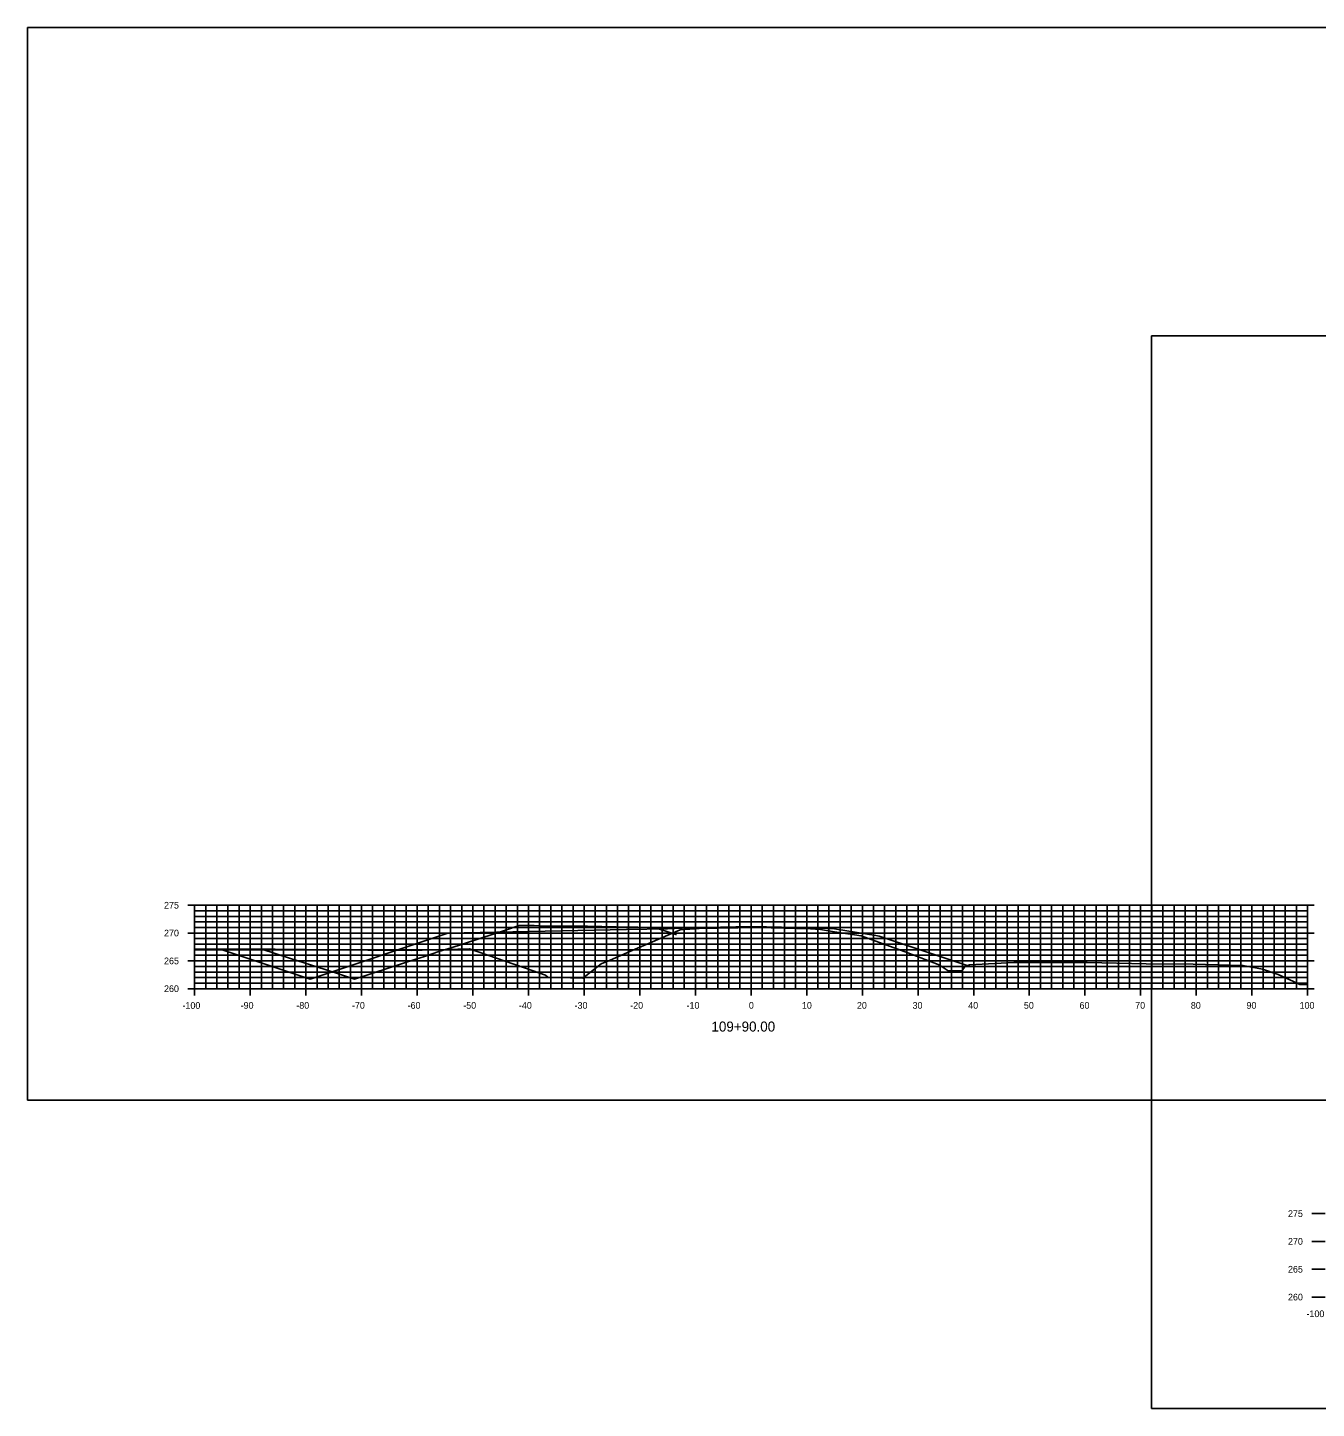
# Model space of a CAD drawing. Extents: x 1661012 to 1662122, y 670053 to 671852.
# Drawn here: x 1661032.7 to 1661264.3, y 671488.8 to 671736.9 of the extents above; entities that cross this region are included whole.
import ezdxf

# ---------------------------------------------------------------- set-up
doc = ezdxf.new("R2010")
doc.units = 0
for name, color, linetype in [('R_Concrete', 7, 'Continuous'), ('R_Concrete Hidden', 7, 'Continuous'), ('R_Erosion', 7, 'Continuous'), ('R_Exist Surface', 7, 'Continuous'), ('R_Proposed Road', 7, 'Continuous'), ('R_ROW Annot', 7, 'Continuous')]:
    doc.layers.add(name, color=color, linetype=linetype)

msp = doc.modelspace()

# ---------------------------------------------------------------- linework, layer by layer
at = {"layer": 'R_Concrete'}
for p, q in [((1661061.47, 671579.25), (1661063.87, 671579.25)), ((1661062.67, 671579.25), (1661262.67, 671579.25)), ((1661062.67, 671564.25), (1661062.67, 671579.25)), ((1661062.67, 671564.25), (1661062.67, 671579.25)), ((1661064.67, 671564.25), (1661064.67, 671579.25)), ((1661066.67, 671564.25), (1661066.67, 671579.25)), ((1661068.67, 671564.25), (1661068.67, 671579.25)), ((1661070.67, 671564.25), (1661070.67, 671579.25)), ((1661072.67, 671564.25), (1661072.67, 671579.25)), ((1661074.67, 671564.25), (1661074.67, 671579.25)), ((1661076.67, 671564.25), (1661076.67, 671579.25)), ((1661078.67, 671564.25), (1661078.67, 671579.25)), ((1661080.67, 671564.25), (1661080.67, 671579.25)), ((1661082.67, 671564.25), (1661082.67, 671579.25)), ((1661084.67, 671564.25), (1661084.67, 671579.25)), ((1661086.67, 671564.25), (1661086.67, 671579.25)), ((1661088.67, 671564.25), (1661088.67, 671579.25)), ((1661090.67, 671564.25), (1661090.67, 671579.25)), ((1661092.67, 671564.25), (1661092.67, 671579.25)), ((1661094.67, 671564.25), (1661094.67, 671579.25)), ((1661096.67, 671564.25), (1661096.67, 671579.25)), ((1661098.67, 671564.25), (1661098.67, 671579.25)), ((1661100.67, 671564.25), (1661100.67, 671579.25)), ((1661102.67, 671564.25), (1661102.67, 671579.25)), ((1661104.67, 671564.25), (1661104.67, 671579.25)), ((1661106.67, 671564.25), (1661106.67, 671579.25)), ((1661108.67, 671564.25), (1661108.67, 671579.25)), ((1661110.67, 671564.25), (1661110.67, 671579.25)), ((1661112.67, 671564.25), (1661112.67, 671579.25)), ((1661114.67, 671564.25), (1661114.67, 671579.25)), ((1661116.67, 671564.25), (1661116.67, 671579.25)), ((1661118.67, 671564.25), (1661118.67, 671579.25)), ((1661120.67, 671564.25), (1661120.67, 671579.25)), ((1661122.67, 671564.25), (1661122.67, 671579.25)), ((1661124.67, 671564.25), (1661124.67, 671579.25)), ((1661126.67, 671564.25), (1661126.67, 671579.25)), ((1661128.67, 671564.25), (1661128.67, 671579.25)), ((1661130.67, 671564.25), (1661130.67, 671579.25)), ((1661132.67, 671564.25), (1661132.67, 671579.25)), ((1661134.67, 671564.25), (1661134.67, 671579.25)), ((1661136.67, 671564.25), (1661136.67, 671579.25)), ((1661138.67, 671564.25), (1661138.67, 671579.25)), ((1661140.67, 671564.25), (1661140.67, 671579.25)), ((1661142.67, 671564.25), (1661142.67, 671579.25)), ((1661144.67, 671564.25), (1661144.67, 671579.25)), ((1661146.67, 671564.25), (1661146.67, 671579.25)), ((1661148.67, 671564.25), (1661148.67, 671579.25)), ((1661150.67, 671564.25), (1661150.67, 671579.25)), ((1661152.67, 671564.25), (1661152.67, 671579.25)), ((1661154.67, 671564.25), (1661154.67, 671579.25)), ((1661156.67, 671564.25), (1661156.67, 671579.25)), ((1661158.67, 671564.25), (1661158.67, 671579.25)), ((1661160.67, 671564.25), (1661160.67, 671579.25)), ((1661162.67, 671564.25), (1661162.67, 671579.25)), ((1661164.67, 671564.25), (1661164.67, 671579.25)), ((1661166.67, 671564.25), (1661166.67, 671579.25)), ((1661168.67, 671564.25), (1661168.67, 671579.25)), ((1661170.67, 671564.25), (1661170.67, 671579.25)), ((1661172.67, 671564.25), (1661172.67, 671579.25)), ((1661174.67, 671564.25), (1661174.67, 671579.25)), ((1661176.67, 671564.25), (1661176.67, 671579.25)), ((1661178.67, 671564.25), (1661178.67, 671579.25)), ((1661180.67, 671564.25), (1661180.67, 671579.25)), ((1661182.67, 671564.25), (1661182.67, 671579.25)), ((1661184.67, 671564.25), (1661184.67, 671579.25)), ((1661186.67, 671564.25), (1661186.67, 671579.25)), ((1661188.67, 671564.25), (1661188.67, 671579.25)), ((1661190.67, 671564.25), (1661190.67, 671579.25)), ((1661192.67, 671564.25), (1661192.67, 671579.25)), ((1661194.67, 671564.25), (1661194.67, 671579.25)), ((1661196.67, 671564.25), (1661196.67, 671579.25)), ((1661198.67, 671564.25), (1661198.67, 671579.25)), ((1661200.67, 671564.25), (1661200.67, 671579.25)), ((1661202.67, 671564.25), (1661202.67, 671579.25)), ((1661204.67, 671564.25), (1661204.67, 671579.25)), ((1661206.67, 671564.25), (1661206.67, 671579.25)), ((1661208.67, 671564.25), (1661208.67, 671579.25)), ((1661210.67, 671564.25), (1661210.67, 671579.25)), ((1661212.67, 671564.25), (1661212.67, 671579.25)), ((1661214.67, 671564.25), (1661214.67, 671579.25)), ((1661216.67, 671564.25), (1661216.67, 671579.25)), ((1661218.67, 671564.25), (1661218.67, 671579.25)), ((1661220.67, 671564.25), (1661220.67, 671579.25)), ((1661222.67, 671564.25), (1661222.67, 671579.25)), ((1661224.67, 671564.25), (1661224.67, 671579.25)), ((1661226.67, 671564.25), (1661226.67, 671579.25)), ((1661228.67, 671564.25), (1661228.67, 671579.25)), ((1661230.67, 671564.25), (1661230.67, 671579.25)), ((1661232.67, 671564.25), (1661232.67, 671579.25)), ((1661234.67, 671564.25), (1661234.67, 671579.25)), ((1661236.67, 671564.25), (1661236.67, 671579.25)), ((1661238.67, 671564.25), (1661238.67, 671579.25)), ((1661240.67, 671564.25), (1661240.67, 671579.25)), ((1661242.67, 671564.25), (1661242.67, 671579.25)), ((1661244.67, 671564.25), (1661244.67, 671579.25)), ((1661246.67, 671564.25), (1661246.67, 671579.25)), ((1661248.67, 671564.25), (1661248.67, 671579.25)), ((1661250.67, 671564.25), (1661250.67, 671579.25)), ((1661252.67, 671564.25), (1661252.67, 671579.25)), ((1661254.67, 671564.25), (1661254.67, 671579.25)), ((1661256.67, 671564.25), (1661256.67, 671579.25)), ((1661258.67, 671564.25), (1661258.67, 671579.25)), ((1661260.67, 671564.25), (1661260.67, 671579.25)), ((1661263.87, 671579.25), (1661261.47, 671579.25)), ((1661262.67, 671564.25), (1661262.67, 671579.25)), ((1661062.67, 671578.25), (1661262.67, 671578.25)), ((1661062.67, 671578.25), (1661063.27, 671578.25)), ((1661062.67, 671577.25), (1661262.67, 671577.25)), ((1661062.67, 671577.25), (1661063.27, 671577.25)), ((1661262.67, 671578.25), (1661262.07, 671578.25)), ((1661262.67, 671577.25), (1661262.07, 671577.25)), ((1661061.47, 671574.25), (1661063.87, 671574.25)), ((1661062.67, 671576.25), (1661262.67, 671576.25)), ((1661062.67, 671576.25), (1661063.27, 671576.25)), ((1661062.67, 671575.25), (1661262.67, 671575.25)), ((1661062.67, 671575.25), (1661063.27, 671575.25)), ((1661062.67, 671574.25), (1661262.67, 671574.25)), ((1661263.87, 671574.25), (1661261.47, 671574.25)), ((1661262.67, 671576.25), (1661262.07, 671576.25)), ((1661262.67, 671575.25), (1661262.07, 671575.25)), ((1661062.67, 671573.25), (1661262.67, 671573.25)), ((1661062.67, 671573.25), (1661063.27, 671573.25)), ((1661062.67, 671572.25), (1661262.67, 671572.25)), ((1661062.67, 671572.25), (1661063.27, 671572.25)), ((1661262.67, 671573.25), (1661262.07, 671573.25)), ((1661262.67, 671572.25), (1661262.07, 671572.25)), ((1661061.47, 671569.25), (1661063.87, 671569.25)), ((1661062.67, 671571.25), (1661262.67, 671571.25)), ((1661062.67, 671571.25), (1661063.27, 671571.25)), ((1661062.67, 671570.25), (1661262.67, 671570.25)), ((1661062.67, 671570.25), (1661063.27, 671570.25)), ((1661062.67, 671569.25), (1661262.67, 671569.25)), ((1661263.87, 671569.25), (1661261.47, 671569.25)), ((1661262.67, 671571.25), (1661262.07, 671571.25)), ((1661262.67, 671570.25), (1661262.07, 671570.25)), ((1661062.67, 671568.25), (1661262.67, 671568.25)), ((1661062.67, 671568.25), (1661063.27, 671568.25)), ((1661062.67, 671567.25), (1661262.67, 671567.25)), ((1661062.67, 671567.25), (1661063.27, 671567.25)), ((1661262.67, 671568.25), (1661262.07, 671568.25)), ((1661262.67, 671567.25), (1661262.07, 671567.25)), ((1661061.47, 671564.25), (1661063.87, 671564.25)), ((1661062.67, 671566.25), (1661262.67, 671566.25)), ((1661062.67, 671566.25), (1661063.27, 671566.25)), ((1661062.67, 671563.05), (1661062.67, 671565.45)), ((1661062.67, 671565.25), (1661262.67, 671565.25)), ((1661062.67, 671565.25), (1661063.27, 671565.25)), ((1661062.67, 671564.25), (1661062.67, 671564.85)), ((1661062.67, 671564.25), (1661262.67, 671564.25)), ((1661064.67, 671564.25), (1661064.67, 671564.85)), ((1661066.67, 671564.25), (1661066.67, 671564.85)), ((1661068.67, 671564.25), (1661068.67, 671564.85)), ((1661070.67, 671564.25), (1661070.67, 671564.85)), ((1661072.67, 671563.05), (1661072.67, 671565.45)), ((1661074.67, 671564.25), (1661074.67, 671564.85)), ((1661076.67, 671564.25), (1661076.67, 671564.85)), ((1661078.67, 671564.25), (1661078.67, 671564.85)), ((1661080.67, 671564.25), (1661080.67, 671564.85)), ((1661082.67, 671563.05), (1661082.67, 671565.45)), ((1661084.67, 671564.25), (1661084.67, 671564.85)), ((1661086.67, 671564.25), (1661086.67, 671564.85)), ((1661088.67, 671564.25), (1661088.67, 671564.85)), ((1661090.67, 671564.25), (1661090.67, 671564.85)), ((1661092.67, 671563.05), (1661092.67, 671565.45)), ((1661094.67, 671564.25), (1661094.67, 671564.85)), ((1661096.67, 671564.25), (1661096.67, 671564.85)), ((1661098.67, 671564.25), (1661098.67, 671564.85)), ((1661100.67, 671564.25), (1661100.67, 671564.85)), ((1661102.67, 671563.05), (1661102.67, 671565.45)), ((1661104.67, 671564.25), (1661104.67, 671564.85)), ((1661106.67, 671564.25), (1661106.67, 671564.85)), ((1661108.67, 671564.25), (1661108.67, 671564.85)), ((1661110.67, 671564.25), (1661110.67, 671564.85)), ((1661112.67, 671563.05), (1661112.67, 671565.45)), ((1661114.67, 671564.25), (1661114.67, 671564.85)), ((1661116.67, 671564.25), (1661116.67, 671564.85)), ((1661118.67, 671564.25), (1661118.67, 671564.85)), ((1661120.67, 671564.25), (1661120.67, 671564.85)), ((1661122.67, 671563.05), (1661122.67, 671565.45)), ((1661124.67, 671564.25), (1661124.67, 671564.85)), ((1661126.67, 671564.25), (1661126.67, 671564.85)), ((1661128.67, 671564.25), (1661128.67, 671564.85)), ((1661130.67, 671564.25), (1661130.67, 671564.85)), ((1661132.67, 671563.05), (1661132.67, 671565.45)), ((1661134.67, 671564.25), (1661134.67, 671564.85)), ((1661136.67, 671564.25), (1661136.67, 671564.85)), ((1661138.67, 671564.25), (1661138.67, 671564.85)), ((1661140.67, 671564.25), (1661140.67, 671564.85)), ((1661142.67, 671563.05), (1661142.67, 671565.45)), ((1661144.67, 671564.25), (1661144.67, 671564.85)), ((1661146.67, 671564.25), (1661146.67, 671564.85)), ((1661148.67, 671564.25), (1661148.67, 671564.85)), ((1661150.67, 671564.25), (1661150.67, 671564.85)), ((1661152.67, 671563.05), (1661152.67, 671565.45)), ((1661154.67, 671564.25), (1661154.67, 671564.85)), ((1661156.67, 671564.25), (1661156.67, 671564.85)), ((1661158.67, 671564.25), (1661158.67, 671564.85)), ((1661160.67, 671564.25), (1661160.67, 671564.85)), ((1661162.67, 671563.05), (1661162.67, 671565.45)), ((1661164.67, 671564.25), (1661164.67, 671564.85)), ((1661166.67, 671564.25), (1661166.67, 671564.85)), ((1661168.67, 671564.25), (1661168.67, 671564.85)), ((1661170.67, 671564.25), (1661170.67, 671564.85)), ((1661172.67, 671563.05), (1661172.67, 671565.45)), ((1661174.67, 671564.25), (1661174.67, 671564.85)), ((1661176.67, 671564.25), (1661176.67, 671564.85)), ((1661178.67, 671564.25), (1661178.67, 671564.85)), ((1661180.67, 671564.25), (1661180.67, 671564.85)), ((1661182.67, 671563.05), (1661182.67, 671565.45)), ((1661184.67, 671564.25), (1661184.67, 671564.85)), ((1661186.67, 671564.25), (1661186.67, 671564.85)), ((1661188.67, 671564.25), (1661188.67, 671564.85)), ((1661190.67, 671564.25), (1661190.67, 671564.85)), ((1661192.67, 671563.05), (1661192.67, 671565.45)), ((1661194.67, 671564.25), (1661194.67, 671564.85)), ((1661196.67, 671564.25), (1661196.67, 671564.85)), ((1661198.67, 671564.25), (1661198.67, 671564.85)), ((1661200.67, 671564.25), (1661200.67, 671564.85)), ((1661202.67, 671563.05), (1661202.67, 671565.45)), ((1661204.67, 671564.25), (1661204.67, 671564.85)), ((1661206.67, 671564.25), (1661206.67, 671564.85)), ((1661208.67, 671564.25), (1661208.67, 671564.85)), ((1661210.67, 671564.25), (1661210.67, 671564.85)), ((1661212.67, 671563.05), (1661212.67, 671565.45)), ((1661214.67, 671564.25), (1661214.67, 671564.85)), ((1661216.67, 671564.25), (1661216.67, 671564.85)), ((1661218.67, 671564.25), (1661218.67, 671564.85)), ((1661220.67, 671564.25), (1661220.67, 671564.85)), ((1661222.67, 671563.05), (1661222.67, 671565.45)), ((1661224.67, 671564.25), (1661224.67, 671564.85)), ((1661226.67, 671564.25), (1661226.67, 671564.85)), ((1661228.67, 671564.25), (1661228.67, 671564.85)), ((1661230.67, 671564.25), (1661230.67, 671564.85)), ((1661232.67, 671563.05), (1661232.67, 671565.45)), ((1661234.67, 671564.25), (1661234.67, 671564.85)), ((1661236.67, 671564.25), (1661236.67, 671564.85)), ((1661238.67, 671564.25), (1661238.67, 671564.85)), ((1661240.67, 671564.25), (1661240.67, 671564.85)), ((1661242.67, 671563.05), (1661242.67, 671565.45)), ((1661244.67, 671564.25), (1661244.67, 671564.85)), ((1661246.67, 671564.25), (1661246.67, 671564.85)), ((1661248.67, 671564.25), (1661248.67, 671564.85)), ((1661250.67, 671564.25), (1661250.67, 671564.85)), ((1661252.67, 671563.05), (1661252.67, 671565.45)), ((1661254.67, 671564.25), (1661254.67, 671564.85)), ((1661256.67, 671564.25), (1661256.67, 671564.85)), ((1661258.67, 671564.25), (1661258.67, 671564.85)), ((1661260.67, 671564.25), (1661260.67, 671564.85)), ((1661263.87, 671564.25), (1661261.47, 671564.25)), ((1661262.67, 671566.25), (1661262.07, 671566.25)), ((1661262.67, 671565.25), (1661262.07, 671565.25)), ((1661262.67, 671563.05), (1661262.67, 671565.45)), ((1661263.44, 671523.84), (1661265.84, 671523.84)), ((1661263.44, 671518.84), (1661265.84, 671518.84)), ((1661263.44, 671513.84), (1661265.84, 671513.84)), ((1661263.44, 671508.84), (1661265.84, 671508.84))]:
    msp.add_line(p, q, dxfattribs=at)
at = {"layer": 'R_Erosion'}
msp.add_lwpolyline([(1661062.67, 671571.36), (1661071.76, 671571.36), (1661076.42, 671571.34), (1661077.16, 671571.35), (1661093.81, 671571.19), (1661099.23, 671571.15), (1661101.65, 671571.11), (1661103.56, 671571.17), (1661112.07, 671571.41), (1661123.32, 671567.5), (1661125.7, 671566.67), (1661126.12, 671566.35), (1661127.94, 671566.26), (1661132.43, 671566.13), (1661134.88, 671568.04), (1661135.73, 671568.71), (1661137.37, 671569.41), (1661141.85, 671571.35), (1661144.53, 671572.51), (1661149.94, 671574.84), (1661152.51, 671575.02), (1661154.19, 671575.14), (1661156.66, 671575.16), (1661164.01, 671575.25), (1661170.9, 671575.08), (1661173.33, 671575), (1661174.23, 671574.97), (1661175.12, 671574.91), (1661177.66, 671574.48), (1661182.46, 671573.78), (1661190.82, 671570.67), (1661196.31, 671568.62), (1661197.03, 671568.2), (1661198.08, 671567.47), (1661199.69, 671567.48), (1661200.55, 671567.45), (1661200.9, 671567.96), (1661201.16, 671568.3), (1661201.92, 671568.56), (1661209.88, 671568.95), (1661223.08, 671568.94), (1661233.67, 671568.75), (1661242.09, 671568.68), (1661251.04, 671568.43), (1661254.58, 671567.74), (1661257.38, 671566.79), (1661260.94, 671565.17), (1661261.25, 671565.03), (1661261.62, 671565.01), (1661262.67, 671564.97)], dxfattribs=at)
at = {"layer": 'R_Exist Surface'}
for p, q in [((1661062.67, 671564.25), (1661062.67, 671579.25)), ((1661262.67, 671564.25), (1661262.67, 671579.25)), ((1661062.67, 671564.25), (1661262.67, 671564.25))]:
    msp.add_line(p, q, dxfattribs=at)
at = {"layer": 'R_Proposed Road'}
for points in [[(1661032.67, 671544.25), (1661392.67, 671544.25), (1661392.67, 671736.95), (1661032.67, 671736.95)], [(1661234.64, 671488.84), (1661594.64, 671488.84), (1661594.64, 671681.54), (1661234.64, 671681.54)]]:
    msp.add_lwpolyline(points, close=True, dxfattribs=at)
at = {"layer": 'R_ROW Annot'}
for points in [[(1661067.28, 671571.36), (1661083.41, 671565.98), (1661108.17, 671574.23), (1661140.26, 671574.88), (1661147.67, 671575.02), (1661151.67, 671575.18), (1661162.67, 671575.4), (1661173.67, 671575.18), (1661177.67, 671575.02), (1661185.08, 671573.79), (1661185.67, 671573.69), (1661201.5, 671568.41)], [(1661074.77, 671571.35), (1661079.75, 671569.74), (1661086.15, 671567.68), (1661088.87, 671566.8), (1661091.43, 671565.98), (1661097.65, 671568), (1661102.43, 671569.55), (1661103.98, 671570.06), (1661106.59, 671570.91), (1661108.76, 671571.61), (1661110.8, 671572.27), (1661114.49, 671573.47), (1661117.12, 671574.32), (1661118.52, 671574.77), (1661121.01, 671575.58), (1661122.82, 671575.59), (1661123.05, 671575.59), (1661123.7, 671575.58), (1661124.76, 671575.57), (1661133.28, 671575.47), (1661141.01, 671575.32), (1661142.3, 671575.29), (1661143.51, 671575.27), (1661144.82, 671575.22), (1661145.57, 671575.19), (1661146.58, 671574.85), (1661147.56, 671574.54), (1661148.22, 671574.32), (1661148.51, 671574.23), (1661149.14, 671574.02), (1661149.25, 671573.98)]]:
    msp.add_lwpolyline(points, dxfattribs=at)

# ---------------------------------------------------------------- texts
at = {"layer": 'R_Concrete Hidden'}
for s, height, p in [('275', 1.2, (1661057.18, 671578.65)), ('270', 1.2, (1661057.18, 671573.65)), ('265', 1.2, (1661057.18, 671568.65)), ('260', 1.2, (1661057.18, 671563.65)), ('-100', 1.2, (1661060.49, 671560.65)), ('-90', 1.2, (1661070.95, 671560.65)), ('-80', 1.2, (1661080.95, 671560.65)), ('-70', 1.2, (1661090.95, 671560.65)), ('-60', 1.2, (1661100.95, 671560.65)), ('-50', 1.2, (1661110.95, 671560.65)), ('-40', 1.2, (1661120.95, 671560.65)), ('-30', 1.2, (1661130.95, 671560.65)), ('-20', 1.2, (1661140.95, 671560.65)), ('-10', 1.2, (1661151.07, 671560.65)), ('0', 1.2, (1661162.27, 671560.65)), ('10', 1.2, (1661171.81, 671560.65)), ('20', 1.2, (1661181.69, 671560.65)), ('30', 1.2, (1661191.69, 671560.65)), ('40', 1.2, (1661201.69, 671560.65)), ('50', 1.2, (1661211.69, 671560.65)), ('60', 1.2, (1661221.69, 671560.65)), ('70', 1.2, (1661231.69, 671560.65)), ('80', 1.2, (1661241.69, 671560.65)), ('90', 1.2, (1661251.69, 671560.65)), ('100', 1.2, (1661261.24, 671560.65)), ('109+90.00', 1.8, (1661155.55, 671556.55)), ('275', 1.2, (1661259.15, 671523.24)), ('270', 1.2, (1661259.15, 671518.24)), ('265', 1.2, (1661259.15, 671513.24)), ('260', 1.2, (1661259.15, 671508.24)), ('-100', 1.2, (1661262.47, 671505.24))]:
    msp.add_text(s, height=height, dxfattribs=at).set_placement(p)
at = {"layer": 'R_Exist Surface'}
msp.add_text('-', height=0.0001, dxfattribs=at).set_placement((1661062.67, 671564.25))

doc.saveas('drawing.dxf')
